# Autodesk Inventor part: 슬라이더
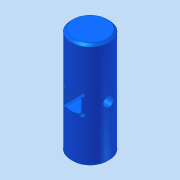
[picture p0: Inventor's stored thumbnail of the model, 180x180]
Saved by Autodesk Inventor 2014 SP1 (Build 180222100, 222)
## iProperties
Company: 한국ATC센터
Created: 2015-04
Part Number: 슬라이더
Document SubType Name: Modeling
Designer: KYOUNG IL JANG
Density: 7.85 g/cm^3
Material: 강
Appearance: 청록색
Author: KYOUNG IL JANG
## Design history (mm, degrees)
sketch "스케치1"
  geometry: C1 r 9 at (0, 0); 1 further point
  constraints: 1 centre point, 1 coincident
  dimensions: "d0" = 18 diameter of C1
extrude "돌출1" new body sketch "스케치1" stored distance "d1" = 50; taper "d2" = 0 deg
node "작업 평면1"
sketch "스케치3"
  geometry: L1 (4, 25)-(-4, 25); L2 (-4, 25)-(-4, -25); L3 (-4, -25)-(4, -25); L4 (4, -25)-(4, 25); 3 further points
  constraints: 8 end point, 2 midpoint, 2 parallel, 1 horizontal, 1 horizontal alignment, 1 perpendicular, 1 vertical alignment
  dimensions: "d5" = 8 distance of L1.start L1.end; "d6" = 50 distance of L1.end L2.end
extrude "돌출3" cut sketch "스케치3" stored distance "d7" = 8; taper "d8" = 0 deg
sketch "스케치4"
  geometry: 5 further points
hole "구멍1" sketch "스케치4" at (4, 4), (-4, 4), (-4, -4), (4, -4) diameter "d9" = 2; stored, may be unused: countersink angle "d13" = 90 deg, drill point angle "d15" = 118 deg; dims "d10" = 6, "d11" = 4, "d12" = 2, "d14" = 8
node "작업 평면2"
sketch "스케치5"
  geometry: 1 further point
hole "구멍2" sketch "스케치5" at (0, 0) diameter "d16" = 5; stored, may be unused: countersink angle "d20" = 90 deg, drill point angle "d22" = 118 deg; dims "d17" = 6, "d18" = 4, "d19" = 2, "d21" = 8
chamfer "모따기1" distance "d23" = 1; stored, may be unused: second distance "d24" = 2, angle "d25" = 45 deg
node "솔리드1"
mirror "대칭1"
